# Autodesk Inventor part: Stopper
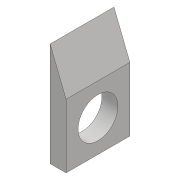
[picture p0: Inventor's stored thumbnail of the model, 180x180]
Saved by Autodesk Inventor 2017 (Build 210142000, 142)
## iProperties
Part Number: Stopper
Material: 一般
Document SubType Name: Modeling
Designer: kyushu-hep
Density: 1 g/cm^3
Appearance: 既定
Author: kyushu-hep
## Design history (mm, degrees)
sketch "スケッチ1"
  geometry: L1 (0, 9.98)-(-2, 4.98); L2 (-2, 4.98)-(-2, -3.02); L3 (-2, -3.02)-(0, -3.02); L4 (0, -3.02)-(0, 9.98); 1 further point
  constraints: 8 end point, 2 perpendicular, 1 vertical
  dimensions: "d0" = 8 distance of L1.end L2.end; "d1" = 2 distance between parallel lines of L4 L2; "d2" = 5 vertical distance of L1.end L1.start
extrude "押し出し1" new body sketch "スケッチ1" distance "d3" = 8; taper "d4" = 0 deg
sketch "スケッチ2"
  geometry: L1 (8, 0)-(8, 8) reference; L2 (8, 0)-(-5, 0) reference; C1 r 2.5 at (4, 4); 1 further point
  constraints: 1 centre point
  dimensions: "d5" = 5 diameter of C1; "d6" = 4 distance from line of L1 C1.centre; "d7" = 4 distance from line of L2 C1.centre
extrude "押し出し2" cut sketch "スケッチ2" distance "d8" = 2; taper "d9" = 0 deg
node "ソリッド1"
